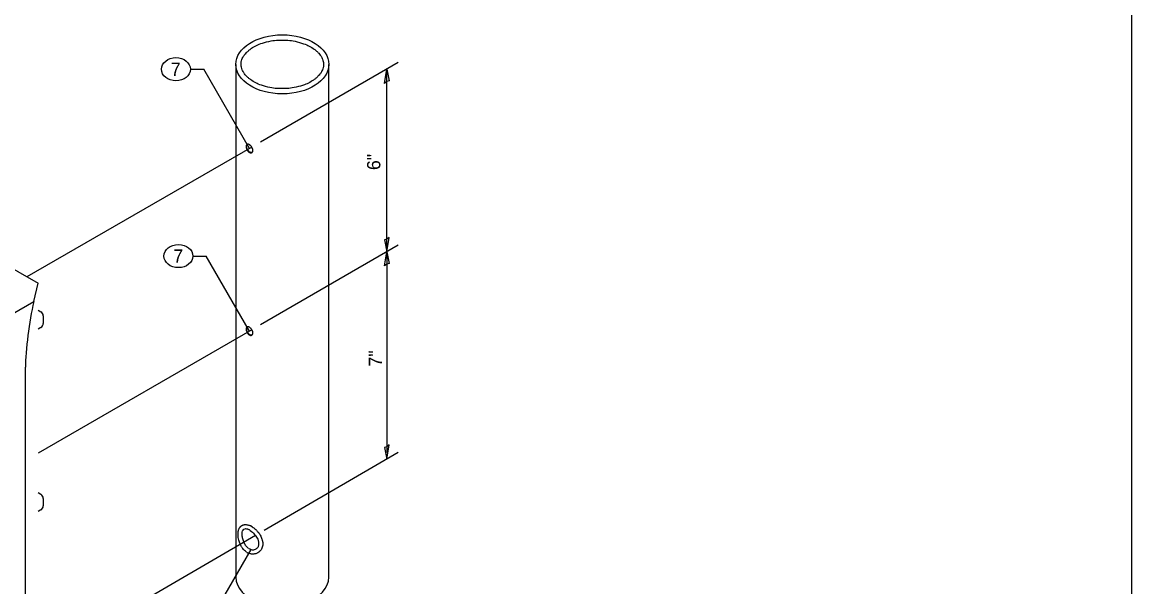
# Model space of a CAD drawing. Extents: x 99862 to 103151, y 100000 to 105076.
# Drawn here: x 101811 to 103151, y 100686 to 101368 of the extents above; entities that cross this region are included whole.
import ezdxf

# ---------------------------------------------------------------- set-up
doc = ezdxf.new("R2010")
doc.units = 0
for name, color, linetype in [('Level 1', 7, 'Continuous'), ('Level 15', 7, 'Continuous'), ('Level 16', 7, 'Continuous'), ('Level 20', 7, 'Continuous'), ('Level 31', 7, 'Continuous'), ('Level 33', 7, 'Continuous')]:
    doc.layers.add(name, color=color, linetype=linetype)

msp = doc.modelspace()

# ---------------------------------------------------------------- linework, layer by layer
at = {"layer": 'Level 1'}
msp.add_lwpolyline([(99862, 99999.5), (103151, 99999.5), (103151, 102075.5), (99862, 102075.5)], close=True, dxfattribs=at)
at = {"layer": 'Level 15'}
for p, q in [((102265.1, 101319.6), (102098.5, 101223.4)), ((102014, 101311.5), (102030, 101311.5)), ((102085.3, 101215.7), (102030, 101311.5)), ((102251.2, 101091.1), (102251.2, 101311.6)), ((102265.1, 101099.1), (102098.5, 101003)), ((102251.2, 101091.1), (102251.2, 100848.7)), ((102017, 101085.9), (102033, 101085.9)), ((102085.3, 100995.3), (102033, 101085.9)), ((102265, 100848.7), (102102.9, 100754.5)), ((102086.8, 100731.4), (101985.7, 100556.4))]:
    msp.add_line(p, q, dxfattribs=at)
for points in [[(102251.2, 101311.6), (102253.9, 101297.4), (102251.2, 101296.6), (102248.5, 101294.3)], [(102251.2, 101091.1), (102253.9, 101108.4), (102251.2, 101106.1), (102248.5, 101105.3)], [(102251.2, 101091.1), (102253.9, 101077), (102251.2, 101076.1), (102248.5, 101073.9)], [(102251.2, 100840.6), (102253.9, 100857.9), (102251.2, 100855.6), (102248.5, 100854.8)]]:
    msp.add_lwpolyline(points, close=True, dxfattribs=at)
at = {"layer": 'Level 16'}
for p, q in [((102088.1, 101217.4), (101816.6, 101060.7)), ((102088.1, 100997), (101830, 100848)), ((102092.6, 100748.4), (101830, 100595.8))]:
    msp.add_line(p, q, dxfattribs=at)
at = {"layer": 'Level 20'}
for centre in [(101996.5, 101311.5), (101999.5, 101085.9)]:
    msp.add_ellipse(centre, major_axis=(-17.5, 0), ratio=0.8, dxfattribs=at)
at = {"layer": 'Level 31'}
for p, q in [((102068.7, 101317.4), (102068.7, 100698)), ((102181.2, 100698), (102181.2, 101317.4)), ((102088.1, 100990.4), (102088.1, 100990.4))]:
    msp.add_line(p, q, dxfattribs=at)
msp.add_ellipse((102125, 101317.4), major_axis=(56.2, 0), ratio=0.635085, dxfattribs=at)
for centre, major_axis, ratio, start_param, end_param in [((102085.2, 100743.7), (7, -12.2), 0.57735, 2.274085, 2.438304), ((102085.2, 100743.7), (7, -12.2), 0.57735, 5.415678, 5.579896), ((102125, 100698), (56.2, 0), 0.635085, 3.14158, 6.283185)]:
    msp.add_ellipse(centre, major_axis=major_axis, ratio=ratio, start_param=start_param, end_param=end_param, dxfattribs=at)
for points, degree in [([(102075.1, 101317.4), (102075.1, 101315.7), (102075.4, 101314), (102076.5, 101310.6), (102077.3, 101309), (102079.4, 101305.6), (102080.8, 101303.9), (102084.2, 101300.7), (102086.2, 101299.1), (102093.1, 101294.7), (102098.7, 101292.3), (102111, 101289), (102117.7, 101288.1), (102131.5, 101288.1), (102138.3, 101288.9), (102150.7, 101292.1), (102156.3, 101294.4), (102163.3, 101298.8), (102165.3, 101300.4), (102168.8, 101303.6), (102170.2, 101305.3), (102172.5, 101308.6), (102173.3, 101310.3), (102174.4, 101313.7), (102174.7, 101315.4), (102174.8, 101318.7), (102174.6, 101320.4), (102173.6, 101323.8), (102172.8, 101325.5), (102170.7, 101328.9), (102169.4, 101330.5), (102166, 101333.8), (102164.1, 101335.4), (102157.3, 101339.8), (102151.8, 101342.2), (102139.5, 101345.6), (102132.8, 101346.6), (102119.1, 101346.7), (102112.3, 101346), (102099.8, 101342.9), (102094.1, 101340.6), (102087, 101336.3), (102085, 101334.7), (102081.4, 101331.5), (102080, 101329.8), (102077.6, 101326.5), (102076.7, 101324.8), (102075.5, 101321.4), (102075.2, 101319.7), (102075.1, 101317.4)], 3), ([(102085.2, 101211.1), (102084.7, 101211.4), (102084.3, 101211.7), (102083.9, 101212.1), (102083.5, 101212.6), (102083.1, 101213.1), (102082.8, 101213.6), (102082.4, 101214.1), (102082.1, 101214.7), (102081.9, 101215.3), (102081.7, 101215.9), (102081.5, 101216.5), (102081.4, 101217.1), (102081.4, 101217.7), (102081.3, 101218.2), (102081.4, 101218.7), (102081.4, 101219.2), (102081.5, 101219.6), (102081.7, 101219.9), (102081.9, 101220.3), (102082.1, 101220.6), (102082.4, 101220.7), (102082.7, 101220.9), (102083.1, 101221), (102083.5, 101221), (102083.9, 101220.9), (102084.3, 101220.8), (102084.7, 101220.6), (102085.2, 101220.4), (102085.6, 101220.1), (102086.1, 101219.8), (102086.5, 101219.4), (102087, 101219), (102087.4, 101218.5), (102087.8, 101218), (102088.1, 101217.4), (102088.4, 101216.9), (102088.8, 101216.3), (102089, 101215.8), (102089.2, 101215.2), (102089.3, 101214.6), (102089.4, 101214), (102089.4, 101213.5), (102089.4, 101213), (102089.3, 101212.5), (102089.2, 101212.1), (102089, 101211.7), (102088.7, 101211.4), (102088.4, 101211.1), (102088.1, 101210.8), (102087.8, 101210.7), (102087.4, 101210.6), (102087, 101210.5), (102086.5, 101210.6), (102086.1, 101210.7), (102085.8, 101210.8), (102085.5, 101210.9), (102085.2, 101211.1)], 3), ([(102085.7, 101211.4), (102085.2, 101211.7), (102084.8, 101212), (102084.4, 101212.4), (102084, 101212.9), (102083.6, 101213.4), (102083.3, 101213.9), (102082.9, 101214.4), (102082.7, 101215), (102082.4, 101215.6), (102082.2, 101216.2), (102082.1, 101216.8), (102082, 101217.4), (102081.9, 101218), (102081.9, 101218.5), (102081.9, 101219), (102081.9, 101219.5), (102082.1, 101219.9), (102082.2, 101220.2), (102082.4, 101220.5), (102082.5, 101220.7), (102082.7, 101220.9)], 3), ([(102088.4, 101211), (102088.2, 101211), (102088.1, 101210.9), (102087.9, 101210.9), (102087.5, 101210.8), (102087, 101210.9), (102086.6, 101211), (102086.3, 101211.1), (102086, 101211.2), (102085.7, 101211.4)], 3), ([(102085.2, 100990.6), (102084.7, 100990.9), (102084.3, 100991.3), (102083.9, 100991.7), (102083.5, 100992.1), (102083.1, 100992.6), (102082.8, 100993.1), (102082.4, 100993.7), (102082.1, 100994.3), (102081.9, 100994.9), (102081.7, 100995.5), (102081.5, 100996.1), (102081.4, 100996.6), (102081.4, 100997.2), (102081.3, 100997.8), (102081.4, 100998.2), (102081.4, 100998.7), (102081.5, 100999.2), (102081.7, 100999.5), (102081.9, 100999.8), (102082.1, 101000.1), (102082.4, 101000.3), (102082.7, 101000.4), (102083.1, 101000.5), (102083.5, 101000.5), (102083.9, 101000.5), (102084.3, 101000.4), (102084.7, 101000.2), (102085.2, 101000), (102085.6, 100999.7), (102086.1, 100999.3), (102086.5, 100998.9), (102087, 100998.5), (102087.4, 100998), (102087.8, 100997.5), (102088.1, 100997), (102088.4, 100996.4), (102088.8, 100995.9), (102089, 100995.3), (102089.2, 100994.7), (102089.3, 100994.2), (102089.4, 100993.6), (102089.4, 100993.1), (102089.4, 100992.6), (102089.3, 100992.1), (102089.2, 100991.7), (102089, 100991.3), (102088.7, 100990.9), (102088.4, 100990.6), (102088.1, 100990.4), (102087.8, 100990.2), (102087.4, 100990.2), (102087, 100990.1), (102086.5, 100990.1), (102086.1, 100990.3), (102085.8, 100990.3), (102085.5, 100990.5), (102085.2, 100990.6)], 3), ([(102085.7, 100990.9), (102085.2, 100991.2), (102084.8, 100991.6), (102084.4, 100992), (102084, 100992.4), (102083.6, 100992.9), (102083.3, 100993.4), (102082.9, 100994), (102082.7, 100994.6), (102082.4, 100995.2), (102082.2, 100995.8), (102082.1, 100996.4), (102082, 100996.9), (102081.9, 100997.5), (102081.9, 100998.1), (102081.9, 100998.5), (102081.9, 100999), (102082.1, 100999.4), (102082.2, 100999.8), (102082.4, 101000), (102082.5, 101000.2), (102082.7, 101000.4)], 3), ([(102088.4, 100990.6), (102088.2, 100990.5), (102088.1, 100990.5), (102087.9, 100990.5), (102087.5, 100990.4), (102087, 100990.4), (102086.6, 100990.5), (102086.3, 100990.6), (102086, 100990.8), (102085.7, 100990.9)], 3), ([(102081.5, 100728.6), (102079.7, 100729.8), (102078.2, 100731.4), (102076.4, 100733.9), (102075.8, 100734.8), (102075, 100736.2), (102074.8, 100736.6), (102074.3, 100737.6), (102074.1, 100738.1), (102073.1, 100740.5), (102072.5, 100742.5), (102071.7, 100746.4), (102071.5, 100748.3), (102071.5, 100751), (102071.5, 100751.9), (102071.8, 100753.7), (102072, 100754.6), (102072.5, 100756.3), (102072.9, 100757.1), (102073.8, 100758.3), (102074.1, 100758.7), (102074.6, 100759.3), (102074.8, 100759.5), (102075.2, 100759.8), (102075.4, 100760), (102076.1, 100760.5), (102076.6, 100760.7), (102077.5, 100761.1), (102078, 100761.3), (102079.5, 100761.7), (102080.5, 100761.7), (102082.4, 100761.5), (102083.3, 100761.3), (102085, 100760.8), (102085.8, 100760.5), (102086.6, 100760)], 3), ([(102084.3, 100732.7), (102081.9, 100734.4), (102079.9, 100737.3), (102077.2, 100743.7), (102076.5, 100747.3), (102076.5, 100753), (102077.2, 100755.1), (102079.9, 100757), (102081.9, 100756.8), (102084.3, 100755.6)], 3), ([(102088.7, 100758.8), (102090.3, 100757.8), (102091.8, 100756.6), (102094, 100754.5), (102094.7, 100753.7), (102095.7, 100752.5), (102096, 100752.1), (102096.5, 100751.5), (102096.7, 100751.3), (102097, 100750.9), (102097.1, 100750.7), (102098.5, 100748.7), (102099.5, 100746.8), (102100.5, 100743.9), (102100.8, 100742.8), (102101.2, 100740.8), (102101.4, 100739.7), (102101.4, 100736.5), (102100.9, 100734.4), (102099.5, 100731.6), (102099, 100730.8), (102097.9, 100729.6), (102097.6, 100729.2), (102097, 100728.7), (102096.8, 100728.5), (102096.3, 100728.2), (102096.1, 100728), (102095, 100727.3), (102094.1, 100726.8), (102092.1, 100726.2), (102091.1, 100726), (102087.9, 100725.9), (102085.8, 100726.3), (102083.9, 100727.2)], 3), ([(102088.8, 100758.8), (102088, 100759.3), (102087.3, 100759.7), (102086.5, 100760.1)], 2), ([(102086, 100754.6), (102088.5, 100753), (102091.2, 100750.5), (102095.1, 100744.7), (102096.4, 100741.5), (102096.4, 100735.8), (102095.1, 100733.4), (102091.2, 100730.7), (102088.5, 100730.6), (102086, 100731.8)], 3), ([(102081.6, 100728.5), (102082.3, 100728.1), (102083, 100727.6), (102083.8, 100727.2)], 2)]:
    msp.add_open_spline(points, degree=degree, dxfattribs=at)
at = {"layer": 'Level 33'}
for p, q in [((101704, 101125.7), (101830, 101053)), ((101824.8, 101030.9), (101830, 101053)), ((101774.9, 101002.1), (101824.8, 101030.9)), ((101830, 101020.6), (101833.4, 101018.6)), ((101836.2, 101013.8), (101836.2, 101004.6)), ((101833.4, 100999.7), (101830, 100997.7)), ((101814.7, 100602.5), (101814.7, 100951.6)), ((101830, 100800.2), (101833.4, 100798.2)), ((101836.2, 100793.3), (101836.2, 100784.1)), ((101833.4, 100779.3), (101830, 100777.3))]:
    msp.add_line(p, q, dxfattribs=at)
for centre, start, end in [((101830.6, 101013.8), 0, 60), ((101830.6, 101004.6), 300, 0), ((101830.6, 100793.3), 0, 60), ((101830.6, 100784.1), 300, 0)]:
    msp.add_arc(centre, 5.63, start, end, dxfattribs=at)
msp.add_ellipse((101824.8, 100994.1), major_axis=(7.7, 56.2), ratio=0.114691, start_param=0.874148, end_param=2.444944, dxfattribs=at)

# ---------------------------------------------------------------- texts
at = {"layer": 'Level 20'}
for p in [(101990.3, 101303.5), (101993.3, 101077.9)]:
    msp.add_text('7', height=16, dxfattribs=at).set_placement(p)
for s, p in [('6"', (102243.4, 101189.7)), ('7"', (102245.4, 100952.5))]:
    msp.add_text(s, height=16, rotation=90, dxfattribs=at).set_placement(p)

doc.saveas('drawing.dxf')
